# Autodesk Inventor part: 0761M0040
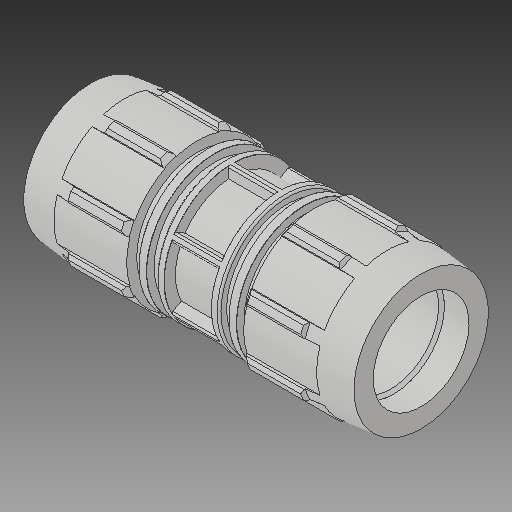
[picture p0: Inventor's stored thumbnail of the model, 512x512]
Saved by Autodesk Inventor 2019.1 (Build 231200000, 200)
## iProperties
Created: 2017-02
Part Number: 0761M0040
Material: Generic
Description: PLASSON REPAIR COUPLER 4'' - 4''
Document SubType Name: Modeling
Designer: KIM
Mass: 2544.89 g
Surface Area: 2949.22 cm^2
Volume: 2544.89 cm^3
Density: 1 g/cm^3
Appearance: Default
Author: KIM
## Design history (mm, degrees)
derived "0761M.ipt"
feature "Solid1::0761M.ipt"
tag "TaggingFeature1"
body "Solid1"
other parameters: "d1" = 392.938, "d2" = 114.1, "d4" = 32.74483, "d5" = 56.134, "d7" = 180.848, "d8" = 135.636, "d9" = 56.134, "d11" = 9.35567, "d12" = 144.6784, "d13" = 120 deg, "d14" = 159.74, "d15" = 6 deg, "d16" = 162.7632, "d19" = 35 deg, "d20" = 17.5 deg, "d21" = 168.18864, "d23" = 0, "d25" = 360 deg, "d27" = 3.61696, "d33" = 0.2, "d34" = 9.0424, "d36" = 0, "d37" = 2.282, "d38" = 2.282, "d40" = 360 deg, "d42" = 70.72884, "d43" = 5.42544, "d46" = 3.423, "d50" = 11.41391, "d51" = 144.6784, "d52" = 11.41391, "d_" = 114.1, "E_" = 180.848, "H_" = 392.938, "l_" = 195.072, "d49" = 32.18349
